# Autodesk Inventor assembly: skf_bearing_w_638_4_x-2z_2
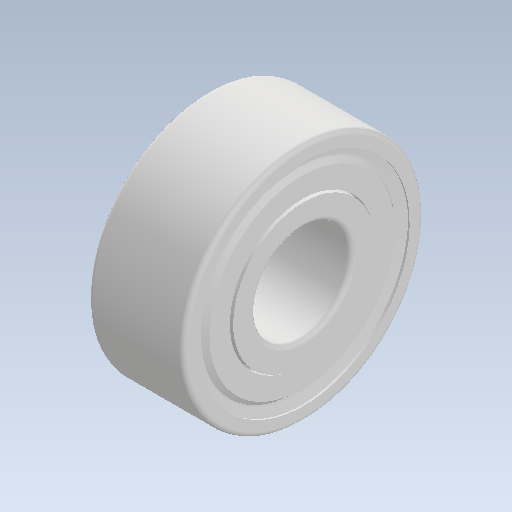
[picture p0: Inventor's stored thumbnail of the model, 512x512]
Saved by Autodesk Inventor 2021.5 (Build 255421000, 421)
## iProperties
Company: TraceParts S.A.
Created: 2023-12
Part Number: skf_bearing_w_638_4_x-2z_2
Checked By: TraceParts S.A.
Catalog Web Link: www.traceparts.com
Document SubType Name: Assembly
Designer: TraceParts
Author: TraceParts
Sending System: TraceParts v2
Major Version: 6.0
Minor Version: 0.0
Format Version: 0.0
Product Id: TraceParts v2
REFERENCE: W 638/4 X-2Z
SUPPLIER: SKF
DESIGN: Stainless steel single row deep groove ball bearing, shields, Bore Ø 4 mm, Outside Ø 10 mm
MASS: 0.00133
TraceParts.PartNumber: 10-28092016-118829
TraceParts.PartVersion: 1.3.2
TraceParts.InstanceId: 10-28092016-118829CEES7WX1G81PVE63ORZI9BIFF
TraceParts.PartTitle: Deep groove ball bearings, single row, stainless steel, shields
TRACEPARTS: TRACEPARTS
TraceParts.PartLanguage: en
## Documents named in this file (6)
- C:\TPO v2\SharedFS\Outgoing\skf_bearing_w_638_4_x-2z_2.iam
- C:\TPO v2\SharedFS\Outgoing\skf_bearing_w_638_4_x-2z_2_01.ipt
- C:\TPO v2\SharedFS\Outgoing\skf_bearing_w_638_4_x-2z_2_02.ipt
- C:\TPO v2\SharedFS\Outgoing\skf_bearing_w_638_4_x-2z_2_03.ipt
- C:\TPO v2\SharedFS\Outgoing\skf_bearing_w_638_4_x-2z_2_04.ipt
- C:\TPO v2\SharedFS\Outgoing\skf_bearing_w_638_4_x-2z_2_05.ipt
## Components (5 placed, 5 different names)
1. skf_bearing_w_638_4_x-2z_2_Temp_1:1
2. skf_bearing_w_638_4_x-2z_2_Temp_2:1
3. skf_bearing_w_638_4_x-2z_2_Temp_3:1
4. skf_bearing_w_638_4_x-2z_2_Temp_4:1
5. skf_bearing_w_638_4_x-2z_2_Temp_5:1
